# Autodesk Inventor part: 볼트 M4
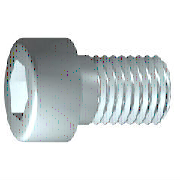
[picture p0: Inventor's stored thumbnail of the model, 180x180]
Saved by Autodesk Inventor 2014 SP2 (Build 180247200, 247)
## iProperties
IsCustomPart: 0
Created: 2018-09
Part Number: 볼트 M4
Material: 스테인리스강
Description: 6각머리 태핑 나사
Document SubType Name: Modeling
Standard: KS B 1003
Standards Organization: KS
Language: ko-KR
Size Designation: M 4 x 10
Categories: <MemberInstance><Categories><Category DisplayName="조임쇠" InternalName="e4da775c-781d-43d5-af7c-5136215cf5a6" Mnemonic="FSTN"><Category DisplayName="볼트" InternalN
Density: 8.08 g/cm^3
Appearance: 반광택
Mass: 2.09412 g
Surface Area: 3.0572 cm^2
Volume: 0.259174 cm^3
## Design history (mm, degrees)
sketch "스케치1"
  geometry: L1 (-1, 0)-(10, 0); L2 (10, 0)-(10, 2); L3 (10, 2)-(1.75, 2); L4 (1.75, 2)-(1.32, 2); L5 (1.32, 2)-(0, 2); L6 (0, 2)-(0, 3.5); L7 (0, 3.5)-(-4, 3.5); L8 (-4, 3.5)-(-4, 1.732); L9 (-4, 1.732)-(-2, 1.732); L10 (-2, 1.732)-(-1, 0); L11 (-6.8, 0)-(12.8, 0) reference; L12 (0, -0.7)-(0, 4.2) reference; L13 (1.75, 2)-(0, 2)
  constraints: 22 end point, 6 parallel, 2 collinear, 2 perpendicular, 1 horizontal, 1 point on line
  dimensions: "d1" = 8.25 distance from line of L3.end L2 (= GEL); "d2" = 0.42952 distance of L4.end L3.end (computed from GAL); "d3" = 4 distance between parallel lines of L8 L6 (= KOH); "d4" = 2 distance of L8.end L9.end (= INTI); "d5" = 60 deg angle of L10 L1; "d6" = 4 diameter of L3 L1 (= GD); "d7" = 4 diameter of L5 L1 (= BDM); "d8" = 3.4641 diameter of L9 L1 (= 1.1547 x SW); "d9" = 7 diameter of L7 L1 (= KOD); "d26" = 10 distance between parallel lines of L12 L2 (= NLG)
revolve "본체" sketch "스케치1" stored, may be unused: angle "d10" = 90 deg
sketch "스케치2"
  geometry: L1 (0, -4.9)-(0, 4.9) reference; L2 (-4.9, 0)-(4.9, 0) reference; L3 (1.732, 0)-(0.866, -1.5); L4 (0.866, -1.5)-(-0.866, -1.5); L5 (-0.866, -1.5)-(-1.732, 0); L6 (-1.732, 0)-(-0.866, 1.5); L7 (-0.866, 1.5)-(0.866, 1.5); L8 (0.866, 1.5)-(1.732, 0); 2 further points
  constraints: 12 end point, 1 coincident, 1 horizontal alignment, 1 point on line, 12 other
extrude "슬롯" join sketch "스케치2" stored distance "d11" = 10; taper "d12" = 0 deg
workplane "Work Plane1"
fillet "Fillet2" dims "d30" = 0.1 (= R)
body "Solid1"
fillet "모깎기1" dims "d17" = 0.4 (= RR)
feature "스레드" dims "d13" = 8.25 (= GEL), "d14" = 0
chamfer "모따기1" distance "d15" = 0.42941 (= -0.5 x SPD + 0.5 x GD); stored, may be unused: second distance "d16" = 0.42941 (= GUL), angle "d27" = 45 deg
other parameters: "GD" = 4 (= NND) [user parameter; used in 2 equation terms], "NLG" = 10 [user parameter; used in 1 equation term], "GEL" = 8.25 [user parameter; used in 2 equation terms], "KOD" = 7 [user parameter; used in 1 equation term], "KOH" = 4 [user parameter; used in 1 equation term], "INTI" = 2 [user parameter; used in 1 equation term], "GAL" = 0.42941 (= 0.61345 x PTC) [user parameter; used in 1 equation term], "GUL" = 0.42941 (= 0.61345 x PTC) [user parameter; used in 1 equation term], "BDM" = 4 (= NND) [user parameter; used in 1 equation term], "SW" = 3 [user parameter; used in 2 equation terms], "RR" = 0.4 [user parameter; used in 1 equation term], "SPD" = 3.14117 (= NND - 1.2269 x PTC) [user parameter; used in 1 equation term], "d19" = 0, "d28" = 0, "d29" = 0, "R" = 0.1 [user parameter; used in 1 equation term], "PHH" = 0.2 [user parameter], "GD1" = 3.14117 (= THREADDIA - 1.2269 x PTC) [user parameter], "THREADDIA" = 4 [user parameter; used in 1 equation term], "FAWI" = 45 deg [user parameter], "TPU" = 14.28571 (computed from PTC) [user parameter], "PTC" = 0.7 [user parameter; used in 5 equation terms], "NND" = 4 [user parameter; used in 3 equation terms], "TOA" = 30 deg [user parameter], "E0" = 3.465 (= 1.155 x SW) [user parameter]
